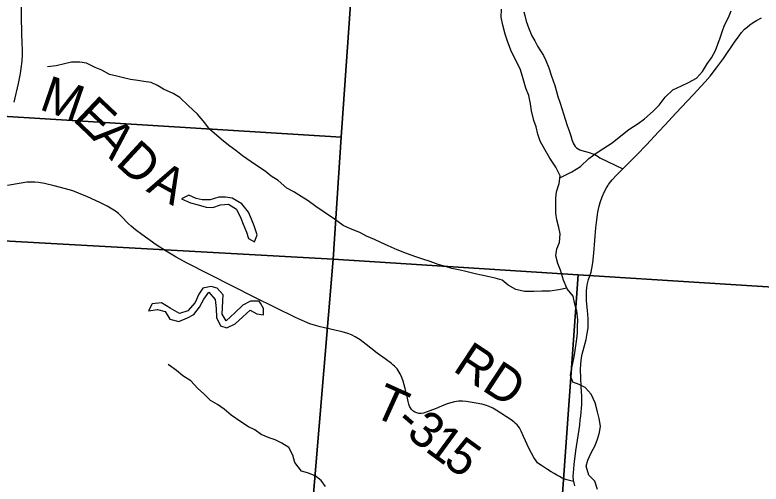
# Model space of a CAD drawing. Extents: x 0 to 34, y 0 to 22.
# Drawn here: x 5.819 to 6.999, y 15.349 to 16.091 of the extents above; entities that cross this region are included whole.
import ezdxf

# ---------------------------------------------------------------- set-up
doc = ezdxf.new("R2010")
doc.units = 0
for name, color, linetype in [('GM_X_Corporation', 7, 'Continuous'), ('GM_X_County_Road', 7, 'Continuous'), ('GM_X_Minor_Lake', 7, 'Continuous'), ('GM_X_Minor_River', 7, 'Continuous'), ('GM_X_Township_Road', 7, 'Continuous'), ('GM_X_Township_Road_Text', 7, 'Continuous')]:
    doc.layers.add(name, color=color, linetype=linetype)

msp = doc.modelspace()

# ---------------------------------------------------------------- linework, layer by layer
at = {"layer": 'GM_X_Corporation'}
for points in [[(6.3912, 16.7203), (7.3858, 16.6558), (7.3548, 16.2394), (7.3238, 15.8259), (7.3098, 15.6422), (6.7101, 15.6799), (6.3225, 15.705), (6.3352, 15.898), (6.3636, 16.3035)], [(6.3636, 16.3035), (6.3352, 15.898), (5.3297, 15.9601), (5.359, 16.3599)], [(6.3352, 15.898), (6.3225, 15.705), (5.3826, 15.7568), (5.3151, 15.7607), (5.3297, 15.9601)], [(6.3225, 15.705), (6.2563, 14.9189), (5.3302, 14.958), (5.3826, 15.7568)], [(6.7101, 15.6799), (6.654, 14.8997), (6.2563, 14.9189), (6.3225, 15.705)], [(7.3098, 15.6422), (7.2299, 14.6588), (7.1543, 14.6607), (7.1673, 14.8728), (6.654, 14.8997), (6.7101, 15.6799)]]:
    msp.add_lwpolyline(points, close=True, dxfattribs=at)
at = {"layer": 'GM_X_County_Road'}
msp.add_lwpolyline([(6.7046, 15.3463), (6.703, 15.353), (6.7026, 15.355), (6.7023, 15.3612), (6.7025, 15.3675), (6.703, 15.3726), (6.7037, 15.3799), (6.7064, 15.4015), (6.7125, 15.4424), (6.7134, 15.4509), (6.714, 15.4567), (6.7155, 15.469), (6.7159, 15.4751), (6.7156, 15.4874), (6.7148, 15.5032), (6.714, 15.5171), (6.7137, 15.5298), (6.714, 15.539), (6.7151, 15.5485), (6.7163, 15.5543), (6.7224, 15.5778), (6.7243, 15.587), (6.7256, 15.596), (6.726, 15.602), (6.726, 15.6108), (6.7248, 15.6235), (6.7233, 15.639), (6.7229, 15.6482), (6.723, 15.654), (6.7237, 15.66), (6.7248, 15.6664), (6.7265, 15.6724), (6.7304, 15.6841), (6.7318, 15.6899), (6.7333, 15.6989), (6.7349, 15.7143), (6.738, 15.7545), (6.7393, 15.7669), (6.7413, 15.7792), (6.7431, 15.7884), (6.7448, 15.7944), (6.7479, 15.8032), (6.7515, 15.8119), (6.7547, 15.8178), (6.7567, 15.8208), (6.7579, 15.8227), (6.7637, 15.8301), (6.77, 15.837), (6.7809, 15.8478), (6.8029, 15.8699), (6.8181, 15.8854), (6.8369, 15.906), (6.8474, 15.9174), (6.8644, 15.9355), (6.892, 15.965), (6.9111, 15.9854), (6.9188, 15.9943), (6.929, 16.0074), (6.9397, 16.0222), (6.9572, 16.048), (6.9646, 16.058), (6.9685, 16.0632), (6.9733, 16.0684), (6.9771, 16.072), (6.9814, 16.0754), (6.9869, 16.0793), (6.9919, 16.0824), (7.0002, 16.0865)], dxfattribs=at)
at = {"layer": 'GM_X_Minor_Lake'}
for p, q in [((6.0943, 15.8062), (6.0826, 15.8004)), ((6.1057, 15.8006), (6.0943, 15.8062)), ((6.0826, 15.8004), (6.0966, 15.7941)), ((6.0966, 15.7941), (6.1088, 15.7908)), ((6.1151, 15.7984), (6.1057, 15.8006)), ((6.128, 15.7985), (6.1151, 15.7984)), ((6.1416, 15.8028), (6.128, 15.7985)), ((6.1518, 15.8029), (6.1416, 15.8028)), ((6.1624, 15.8011), (6.1518, 15.8029)), ((6.178, 15.7925), (6.1624, 15.8011)), ((6.1088, 15.7908), (6.1217, 15.7871)), ((6.1217, 15.7871), (6.1319, 15.7864)), ((6.1319, 15.7864), (6.144, 15.7907)), ((6.144, 15.7907), (6.1568, 15.7916)), ((6.1568, 15.7916), (6.1694, 15.7837)), ((6.1694, 15.7837), (6.1763, 15.7698)), ((6.1883, 15.779), (6.178, 15.7925)), ((6.1933, 15.768), (6.1883, 15.779)), ((6.1763, 15.7698), (6.1802, 15.76)), ((6.1802, 15.76), (6.1852, 15.7475)), ((6.1972, 15.7575), (6.1933, 15.768)), ((6.1852, 15.7475), (6.1883, 15.7377)), ((6.2019, 15.7431), (6.1972, 15.7575)), ((6.1883, 15.7377), (6.1978, 15.7321)), ((6.1978, 15.7321), (6.2004, 15.7391)), ((6.2004, 15.7391), (6.2019, 15.7431)), ((6.116, 15.659), (6.11, 15.6494)), ((6.1292, 15.6617), (6.116, 15.659)), ((6.118, 15.6416), (6.1259, 15.6526)), ((6.1259, 15.6526), (6.1358, 15.641)), ((6.1391, 15.6588), (6.1292, 15.6617)), ((6.1482, 15.6483), (6.1391, 15.6588)), ((6.11, 15.6494), (6.1041, 15.6365)), ((6.1109, 15.629), (6.118, 15.6416)), ((6.1358, 15.641), (6.1374, 15.627)), ((6.1479, 15.6388), (6.1482, 15.6483)), ((6.036, 15.6344), (6.0304, 15.6233)), ((6.0507, 15.6356), (6.036, 15.6344)), ((6.0644, 15.6274), (6.0507, 15.6356)), ((6.1041, 15.6365), (6.0924, 15.6231)), ((6.102, 15.6172), (6.1109, 15.629)), ((6.1473, 15.6278), (6.1479, 15.6388)), ((6.1794, 15.6319), (6.1666, 15.62)), ((6.1914, 15.6384), (6.1794, 15.6319)), ((6.2054, 15.6382), (6.1914, 15.6384)), ((6.2074, 15.635), (6.2054, 15.6382)), ((6.2124, 15.6269), (6.2074, 15.635)), ((6.0304, 15.6233), (6.0444, 15.625)), ((6.0444, 15.625), (6.0565, 15.622)), ((6.0565, 15.622), (6.0638, 15.61)), ((6.0792, 15.6188), (6.0644, 15.6274)), ((6.0924, 15.6231), (6.0792, 15.6188)), ((6.0918, 15.6118), (6.102, 15.6172)), ((6.1374, 15.627), (6.1376, 15.6126)), ((6.147, 15.6176), (6.1473, 15.6278)), ((6.1531, 15.6074), (6.147, 15.6176)), ((6.1666, 15.62), (6.1531, 15.6074)), ((6.1796, 15.6137), (6.1912, 15.624)), ((6.1912, 15.624), (6.2018, 15.6184)), ((6.2018, 15.6184), (6.2121, 15.6166)), ((6.2121, 15.6166), (6.2124, 15.6269)), ((6.0638, 15.61), (6.0782, 15.6063)), ((6.0782, 15.6063), (6.0918, 15.6118)), ((6.1376, 15.6126), (6.1441, 15.5994)), ((6.1675, 15.6026), (6.1796, 15.6137)), ((6.1441, 15.5994), (6.154, 15.5964)), ((6.154, 15.5964), (6.1675, 15.6026))]:
    msp.add_line(p, q, dxfattribs=at)
at = {"layer": 'GM_X_Minor_River'}
for p, q in [((6.9477, 16.0872), (6.9521, 16.0978)), ((6.9417, 16.075), (6.9477, 16.0872)), ((6.938, 16.0643), (6.9417, 16.075)), ((6.9273, 16.0351), (6.9347, 16.0548)), ((6.9347, 16.0548), (6.938, 16.0643)), ((6.921, 16.0232), (6.9273, 16.0351)), ((6.9143, 16.0137), (6.921, 16.0232)), ((5.884, 16.0104), (5.8704, 16.0091)), ((5.8972, 16.0139), (5.884, 16.0104)), ((5.9086, 16.0163), (5.8972, 16.0139)), ((5.9214, 16.0164), (5.9086, 16.0163)), ((5.932, 16.015), (5.9214, 16.0164)), ((5.9461, 16.0079), (5.932, 16.015)), ((5.9563, 16.0035), (5.9461, 16.0079)), ((6.9068, 16.0019), (6.9143, 16.0137)), ((5.9685, 15.9971), (5.9563, 16.0035)), ((5.9803, 15.9942), (5.9685, 15.9971)), ((6.8971, 15.9912), (6.9068, 16.0019)), ((5.9905, 15.9917), (5.9803, 15.9942)), ((6.0019, 15.9891), (5.9905, 15.9917)), ((6.0132, 15.9873), (6.0019, 15.9891)), ((6.0227, 15.9859), (6.0132, 15.9873)), ((6.0344, 15.9841), (6.0227, 15.9859)), ((6.0443, 15.9796), (6.0344, 15.9841)), ((6.8737, 15.9789), (6.8846, 15.9843)), ((6.8846, 15.9843), (6.8971, 15.9912)), ((6.0542, 15.9737), (6.0443, 15.9796)), ((6.0694, 15.9666), (6.0542, 15.9737)), ((6.8474, 15.9612), (6.8598, 15.9727)), ((6.8598, 15.9727), (6.8737, 15.9789)), ((6.0797, 15.9606), (6.0694, 15.9666)), ((6.093, 15.9479), (6.0797, 15.9606)), ((6.838, 15.9486), (6.8474, 15.9612)), ((6.1075, 15.934), (6.093, 15.9479)), ((6.8286, 15.939), (6.838, 15.9486)), ((6.8148, 15.9268), (6.8286, 15.939)), ((6.1194, 15.9205), (6.1075, 15.934)), ((6.805, 15.9195), (6.8148, 15.9268)), ((6.127, 15.9103), (6.1194, 15.9205)), ((6.7903, 15.9099), (6.805, 15.9195)), ((6.1385, 15.9006), (6.127, 15.9103)), ((6.1488, 15.8915), (6.1385, 15.9006)), ((6.7775, 15.8999), (6.7903, 15.9099)), ((6.1587, 15.8833), (6.1488, 15.8915)), ((6.749, 15.8792), (6.764, 15.8888)), ((6.764, 15.8888), (6.7775, 15.8999)), ((6.1682, 15.8766), (6.1587, 15.8833)), ((6.7384, 15.8727), (6.749, 15.8792)), ((6.1792, 15.8683), (6.1682, 15.8766)), ((6.1929, 15.8586), (6.1792, 15.8683)), ((6.7271, 15.8638), (6.7384, 15.8727)), ((6.2044, 15.8508), (6.1929, 15.8586)), ((6.7136, 15.8516), (6.7271, 15.8638)), ((6.2146, 15.844), (6.2044, 15.8508)), ((6.2245, 15.8362), (6.2146, 15.844)), ((6.6812, 15.8337), (6.7001, 15.8428)), ((6.7001, 15.8428), (6.7136, 15.8516)), ((6.2356, 15.8294), (6.2245, 15.8362)), ((6.2489, 15.8171), (6.2356, 15.8294)), ((6.2603, 15.8111), (6.2489, 15.8171)), ((6.2717, 15.804), (6.2603, 15.8111)), ((6.2828, 15.7969), (6.2717, 15.804)), ((6.295, 15.7879), (6.2828, 15.7969)), ((6.3079, 15.7789), (6.295, 15.7879)), ((6.3243, 15.7681), (6.3079, 15.7789)), ((6.3383, 15.758), (6.3243, 15.7681)), ((6.3497, 15.7528), (6.3383, 15.758)), ((6.3645, 15.7469), (6.3497, 15.7528)), ((6.3752, 15.7413), (6.3645, 15.7469)), ((6.3877, 15.7361), (6.3752, 15.7413)), ((6.398, 15.7313), (6.3877, 15.7361)), ((6.4094, 15.7261), (6.398, 15.7313)), ((6.4238, 15.7197), (6.4094, 15.7261)), ((6.4386, 15.7138), (6.4238, 15.7197)), ((6.4534, 15.7083), (6.4386, 15.7138)), ((6.464, 15.705), (6.4534, 15.7083)), ((6.4758, 15.7013), (6.464, 15.705)), ((6.4887, 15.6965), (6.4758, 15.7013)), ((6.5001, 15.6932), (6.4887, 15.6965)), ((6.5103, 15.6898), (6.5001, 15.6932)), ((6.5206, 15.6877), (6.5103, 15.6898)), ((6.53, 15.6858), (6.5206, 15.6877)), ((6.5471, 15.6815), (6.53, 15.6858)), ((6.557, 15.6793), (6.5471, 15.6815)), ((6.5691, 15.6767), (6.557, 15.6793)), ((6.5786, 15.6749), (6.5691, 15.6767)), ((6.5896, 15.6716), (6.5786, 15.6749)), ((6.5995, 15.6637), (6.5896, 15.6716)), ((6.6113, 15.6567), (6.5995, 15.6637)), ((6.6249, 15.6534), (6.6113, 15.6567)), ((6.6397, 15.6535), (6.6249, 15.6534)), ((6.6525, 15.654), (6.6397, 15.6535)), ((6.665, 15.6541), (6.6525, 15.654)), ((6.6794, 15.6565), (6.665, 15.6541)), ((6.6922, 15.6588), (6.6794, 15.6565)), ((6.0747, 15.5286), (6.0614, 15.538)), ((6.0846, 15.5204), (6.0747, 15.5286)), ((6.0972, 15.5121), (6.0846, 15.5204)), ((6.1079, 15.5005), (6.0972, 15.5121)), ((6.1178, 15.4919), (6.1079, 15.5005)), ((6.1285, 15.481), (6.1178, 15.4919)), ((6.1395, 15.475), (6.1285, 15.481)), ((6.1502, 15.4675), (6.1395, 15.475)), ((6.1612, 15.4582), (6.1502, 15.4675)), ((6.1765, 15.4477), (6.1612, 15.4582)), ((6.1886, 15.4395), (6.1765, 15.4477)), ((6.1985, 15.4346), (6.1886, 15.4395)), ((6.2084, 15.4275), (6.1985, 15.4346)), ((6.2209, 15.4223), (6.2084, 15.4275)), ((6.2304, 15.419), (6.2209, 15.4223)), ((6.2411, 15.4138), (6.2304, 15.419)), ((6.2525, 15.4067), (6.2411, 15.4138)), ((6.2586, 15.395), (6.2525, 15.4067)), ((6.2618, 15.3833), (6.2586, 15.395)), ((6.2721, 15.3697), (6.2618, 15.3833)), ((6.282, 15.3668), (6.2721, 15.3697)), ((6.2937, 15.362), (6.282, 15.3668)), ((6.3033, 15.3549), (6.2937, 15.362)), ((6.3101, 15.3451), (6.3033, 15.3549))]:
    msp.add_line(p, q, dxfattribs=at)
for points in [[(6.6749, 15.7777), (6.6747, 15.8012), (6.6758, 15.8115), (6.6798, 15.8244), (6.6816, 15.8365), (6.6747, 15.8501), (6.6651, 15.8644), (6.6574, 15.8784), (6.6501, 15.8916), (6.6462, 15.9025), (6.6435, 15.9139), (6.6396, 15.9244), (6.6361, 15.9392), (6.6344, 15.9505), (6.6317, 15.9638), (6.6274, 15.9755), (6.6228, 15.9898), (6.6188, 16.0042), (6.6119, 16.0185), (6.6046, 16.0329), (6.5988, 16.048), (6.5945, 16.0608), (6.5906, 16.0748), (6.5882, 16.0877), (6.5885, 16.1002)], [(6.7408, 15.3407), (6.7365, 15.3535), (6.7269, 15.3633), (6.7227, 15.3776), (6.7252, 15.3871), (6.7308, 15.3985), (6.7368, 15.41), (6.7405, 15.4199), (6.7438, 15.4305), (6.7452, 15.4407), (6.7432, 15.4528), (6.7405, 15.4634), (6.7369, 15.4778), (6.7304, 15.4914), (6.7208, 15.5019), (6.7113, 15.5064), (6.7018, 15.5104), (6.6976, 15.5206), (6.6994, 15.5309), (6.7016, 15.5404), (6.7038, 15.5503), (6.7052, 15.5605), (6.7077, 15.5787), (6.7087, 15.5882), (6.709, 15.5977), (6.7093, 15.609), (6.7077, 15.623), (6.7049, 15.6336), (6.7022, 15.6465), (6.6926, 15.6578), (6.6868, 15.6717), (6.6821, 15.6876), (6.6779, 15.6978), (6.6744, 15.7099), (6.6762, 15.7213), (6.6802, 15.7312), (6.6813, 15.7448), (6.6793, 15.755), (6.6761, 15.7668), (6.6749, 15.7777)]]:
    msp.add_lwpolyline(points, dxfattribs=at)
at = {"layer": 'GM_X_Township_Road'}
for points in [[(5.8176, 15.9531), (5.8244, 15.9825), (5.8275, 15.9987), (5.829, 16.0064), (5.8302, 16.0179), (5.8307, 16.028), (5.8308, 16.0353), (5.8304, 16.0471), (5.8301, 16.0614), (5.8292, 16.089), (5.8287, 16.1218)], [(6.6242, 16.0962), (6.6255, 16.0902), (6.6279, 16.0812), (6.632, 16.0694), (6.6368, 16.0583), (6.6413, 16.0501), (6.6459, 16.0419), (6.6506, 16.0345), (6.6549, 16.0267), (6.659, 16.0192), (6.6638, 16.0072), (6.668, 15.9942), (6.673, 15.9793), (6.6759, 15.9701), (6.678, 15.962), (6.6814, 15.9517), (6.6869, 15.9347), (6.6928, 15.9163), (6.6944, 15.9119), (6.6965, 15.9063), (6.6973, 15.9032), (6.6984, 15.9), (6.7002, 15.894), (6.7022, 15.8882), (6.7036, 15.8857), (6.7054, 15.8832), (6.7075, 15.881), (6.71, 15.8792), (6.7128, 15.8778), (6.7157, 15.8767), (6.7276, 15.8734), (6.7334, 15.8713), (6.7363, 15.8701), (6.739, 15.8686), (6.7416, 15.867), (6.7441, 15.865), (6.7686, 15.8536), (6.7809, 15.8478)], [(6.703, 15.353), (6.6982, 15.3542), (6.6922, 15.3557), (6.6848, 15.3584), (6.6802, 15.3609), (6.6763, 15.363), (6.6722, 15.3656), (6.6674, 15.3685), (6.6617, 15.372), (6.6567, 15.3751), (6.652, 15.3782), (6.6479, 15.3811), (6.6458, 15.3829), (6.6433, 15.3858), (6.6399, 15.3913), (6.6325, 15.4048), (6.6236, 15.4244), (6.6198, 15.4326), (6.617, 15.4381), (6.6153, 15.4406), (6.6133, 15.443), (6.6111, 15.4451), (6.6088, 15.4472), (6.6038, 15.4509), (6.5805, 15.4662), (6.575, 15.4692), (6.5694, 15.4718), (6.5635, 15.4738), (6.5575, 15.4753), (6.5453, 15.4777), (6.533, 15.4796), (6.5268, 15.4801), (6.5206, 15.48), (6.5145, 15.4792), (6.5084, 15.4777), (6.5025, 15.4758), (6.4938, 15.4724), (6.4854, 15.4685), (6.4754, 15.4647), (6.4693, 15.4626), (6.4653, 15.4614), (6.4618, 15.4609), (6.4598, 15.4608), (6.4581, 15.4609), (6.4549, 15.4616), (6.4515, 15.463), (6.4486, 15.465), (6.4464, 15.4671), (6.4447, 15.4697), (6.4434, 15.4722), (6.4422, 15.4754), (6.4411, 15.4796), (6.4399, 15.4849), (6.4364, 15.5), (6.4332, 15.512), (6.4311, 15.5178), (6.4285, 15.5235), (6.4253, 15.5288), (6.4235, 15.5312), (6.4215, 15.5336), (6.4193, 15.5358), (6.417, 15.5378), (6.4146, 15.5398), (6.4044, 15.5469), (6.3919, 15.5561), (6.3748, 15.5696), (6.3649, 15.577), (6.3571, 15.5821), (6.3516, 15.585), (6.3458, 15.5872), (6.3368, 15.5898), (6.3065, 15.5967), (6.302, 15.5978), (6.2945, 15.5997), (6.2856, 15.6026), (6.2769, 15.606), (6.2628, 15.6124), (6.1987, 15.6442), (6.1265, 15.6804), (6.0905, 15.6988), (6.0742, 15.7078), (6.0582, 15.7174), (6.0426, 15.7276), (6.0197, 15.7436), (6.0097, 15.7511), (6.0026, 15.7571), (5.9981, 15.7613), (5.9873, 15.7725), (5.9827, 15.7768), (5.9779, 15.7806), (5.9728, 15.7841), (5.9647, 15.7887), (5.9535, 15.7942), (5.9338, 15.8034), (5.9195, 15.8094), (5.9107, 15.8127), (5.8988, 15.8163), (5.8808, 15.821), (5.8656, 15.8244), (5.8564, 15.826), (5.8502, 15.8266), (5.844, 15.8267), (5.8378, 15.8264), (5.8286, 15.8252), (5.8072, 15.8213)]]:
    msp.add_lwpolyline(points, dxfattribs=at)

# ---------------------------------------------------------------- texts
at = {"layer": 'GM_X_Township_Road_Text'}
for s, height, rotation, p in [('M', 0.0568, 341.0074, (5.8558, 15.9423)), ('E', 0.0568, 316.5365, (5.9087, 15.9255)), ('A', 0.0568, 311.8096, (5.9387, 15.8971)), ('D', 0.0568, 317.3104, (5.9762, 15.8556)), ('A', 0.0568, 331.3239, (6.0252, 15.8129)), ('RD', 0.05682, 326.5838, (6.5099, 15.5293)), ('T', 0.0568, 335.6511, (6.382, 15.4581)), ('-', 0.0568, 319.077, (6.4171, 15.4429)), ('3', 0.0568, 320.9813, (6.4363, 15.4263)), ('1', 0.0568, 323.782, (6.4659, 15.4024)), ('5', 0.0568, 324.1616, (6.4945, 15.3815))]:
    msp.add_text(s, height=height, rotation=rotation, dxfattribs=at).set_placement(p)

doc.saveas('drawing.dxf')
